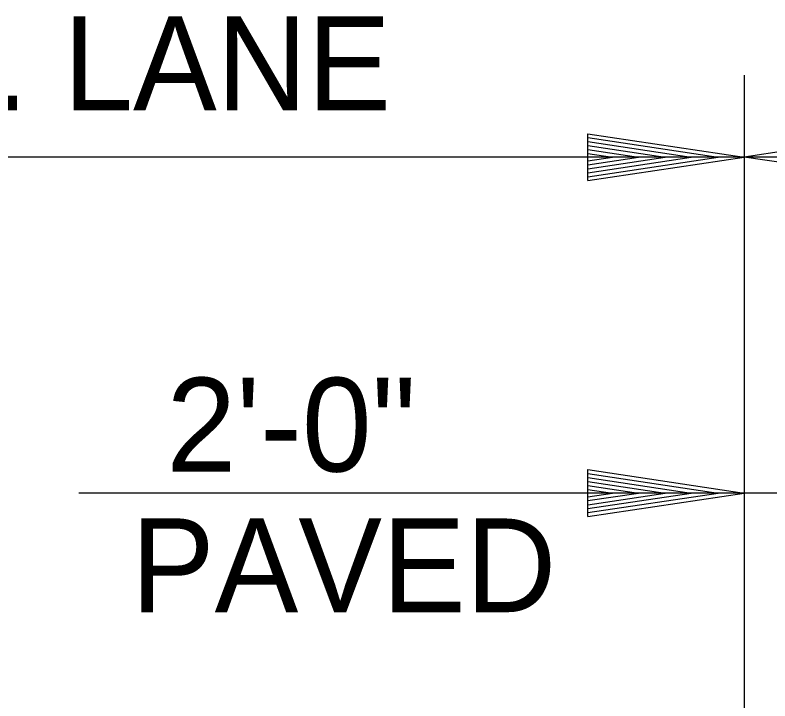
# Model space of a CAD drawing. Extents: x 2829243 to 2838161, y 467639 to 474695.
# Drawn here: x 2833855.27 to 2833903.55, y 469091.52 to 469135.41 of the extents above; entities that cross this region are included whole.
import ezdxf

# ---------------------------------------------------------------- set-up
doc = ezdxf.new("R2010")
doc.units = 0
doc.layers.add('R_Dimension', color=7, linetype='Continuous')
doc.layers.add('R_Draft', color=7, linetype='Continuous')

msp = doc.modelspace()

# ---------------------------------------------------------------- linework, layer by layer
at = {"layer": 'R_Dimension'}
for p, q in [((2833901.9, 469131.572), (2833901.9, 469075.825)), ((2833891.9, 469127.818), (2833901.9, 469126.318)), ((2833891.9, 469124.818), (2833891.9, 469127.818)), ((2833911.9, 469127.818), (2833901.9, 469126.318)), ((2833891.9, 469127.568), (2833900.23, 469126.318)), ((2833891.9, 469127.313), (2833898.51, 469126.318)), ((2833891.9, 469127.063), (2833896.845, 469126.318)), ((2833891.9, 469126.808), (2833895.15, 469126.318)), ((2833901.9, 469126.318), (2833791.9, 469126.318)), ((2833891.9, 469126.553), (2833893.48, 469126.318)), ((2833891.9, 469124.818), (2833901.9, 469126.318)), ((2833891.9, 469125.833), (2833895.15, 469126.318)), ((2833891.9, 469125.323), (2833898.51, 469126.318)), ((2833891.9, 469125.068), (2833900.23, 469126.318)), ((2833891.9, 469125.573), (2833896.845, 469126.318)), ((2833891.9, 469126.083), (2833893.48, 469126.318)), ((2833941.9, 469126.318), (2833901.9, 469126.318)), ((2833911.9, 469124.818), (2833901.9, 469126.318))]:
    msp.add_line(p, q, dxfattribs=at)
at = {"layer": 'R_Draft'}
for p, q in [((2833891.9, 469106.323), (2833901.9, 469104.823)), ((2833891.9, 469103.323), (2833891.9, 469106.323)), ((2833891.9, 469106.073), (2833900.23, 469104.823)), ((2833891.9, 469105.818), (2833898.51, 469104.823)), ((2833891.9, 469105.568), (2833896.845, 469104.823)), ((2833891.9, 469105.313), (2833895.15, 469104.823)), ((2833891.9, 469105.058), (2833893.48, 469104.823)), ((2833921.9, 469104.823), (2833859.355, 469104.823)), ((2833891.9, 469103.323), (2833901.9, 469104.823)), ((2833891.9, 469104.338), (2833895.15, 469104.823)), ((2833891.9, 469103.828), (2833898.51, 469104.823)), ((2833891.9, 469103.573), (2833900.23, 469104.823)), ((2833891.9, 469104.078), (2833896.845, 469104.823)), ((2833891.9, 469104.588), (2833893.48, 469104.823))]:
    msp.add_line(p, q, dxfattribs=at)

# ---------------------------------------------------------------- texts
at = {"layer": 'R_Dimension'}
msp.add_text('11\'-0" PROP. LANE', height=6, dxfattribs=at).set_placement((2833808.49, 469129.318))
at = {"layer": 'R_Draft'}
for s, p in [('2\'-0"', (2833864.949, 469106.201)), ('PAVED', (2833862.682, 469097.201))]:
    msp.add_text(s, height=6, rotation=360, dxfattribs=at).set_placement(p)

doc.saveas('drawing.dxf')
